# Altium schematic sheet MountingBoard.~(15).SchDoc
size Legal; Organization: Altium Limited; Address1: 3 Minna Close; Address2: Belrose; Address3: NSW 2085; Address4: Australia
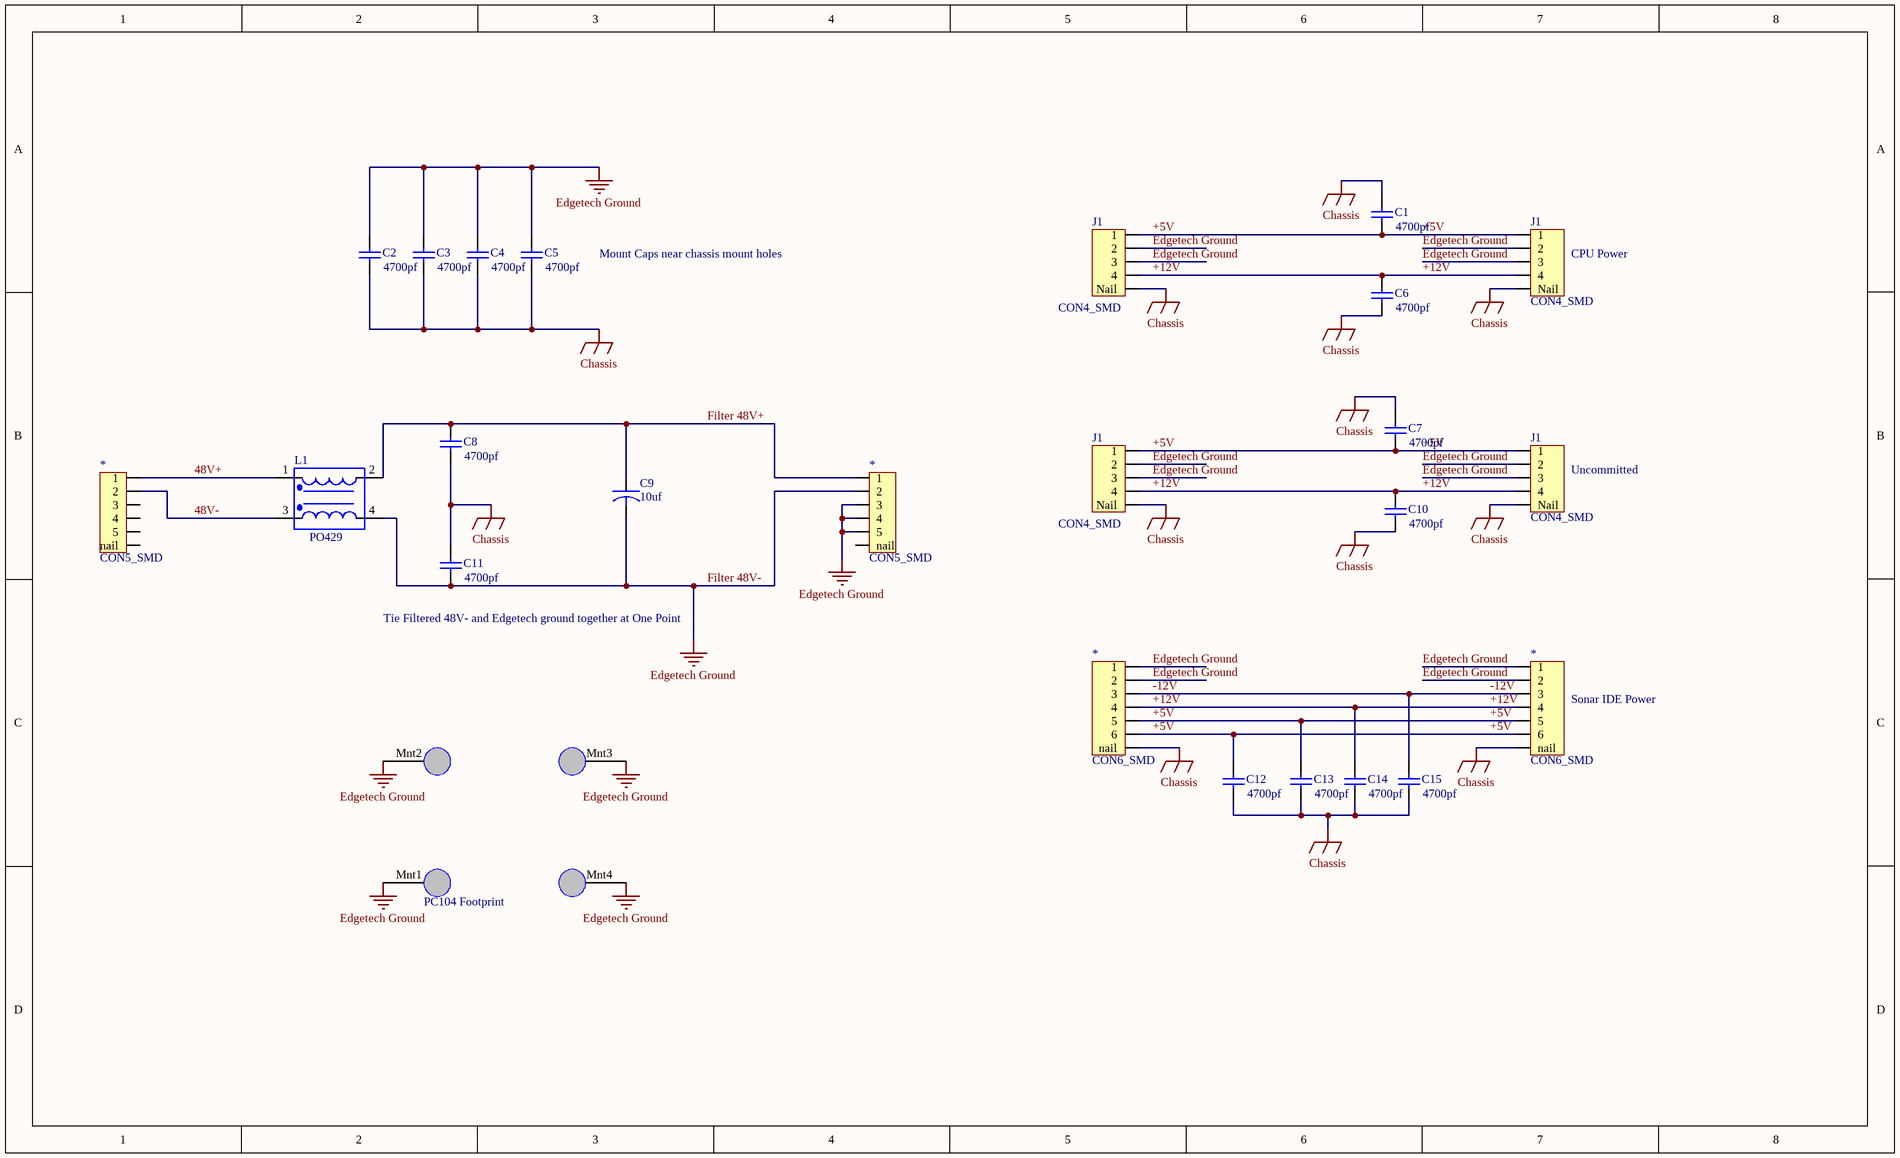
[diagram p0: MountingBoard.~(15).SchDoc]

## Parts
(Parts that share a designator on the sheet are numbered #1, #2 ... from top to bottom, then left to right.)
*#1  CON5_SMD  [Microfit3-1x5 SMT RA Nail]
*#2  CON5_SMD  [Microfit3-1x5 SMT RA Nail]
*#3  CON6_SMD  [Microfit3-1x6 SMT RA Nail]
*#4  CON6_SMD  [Microfit3-1x6 SMT RA Nail]
C1  value 4700pf  [7163]  (hidden comment: Cap Semi)
C2  value 4700pf  [7163]  (hidden comment: Cap Semi)
C3  value 4700pf  [7163]  (hidden comment: Cap Semi)
C4  value 4700pf  [7163]  (hidden comment: Cap Semi)
C5  value 4700pf  [7163]  (hidden comment: Cap Semi)
C6  value 4700pf  [7163]  (hidden comment: Cap Semi)
C7  value 4700pf  [7163]  (hidden comment: Cap Semi)
C8  value 4700pf  [7163]  (hidden comment: Cap Semi)
C9  10uf  [CAPSTICK-CS4-7-SMD]
C10  value 4700pf  [7163]  (hidden comment: Cap Semi)
C11  value 4700pf  [7163]  (hidden comment: Cap Semi)
C12  value 4700pf  [7163]  (hidden comment: Cap Semi)
C13  value 4700pf  [7163]  (hidden comment: Cap Semi)
C14  value 4700pf  [7163]  (hidden comment: Cap Semi)
C15  value 4700pf  [7163]  (hidden comment: Cap Semi)
F1  PC104 Footprint  [PC104 Footprint]
J1#1  CON4_SMD  [Microfit3-1x4 SMT RA Nail]
J1#2  CON4_SMD  [Microfit3-1x4 SMT RA Nail]
J1#3  CON4_SMD  [Microfit3-1x4 SMT RA Nail]
J1#4  CON4_SMD  [Microfit3-1x4 SMT RA Nail]
L1  ManufPartNo: PO429  [Pulse_BigFoot]

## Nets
Chassis: *#3.nail *#4.nail C1.2 C2.1 C3.1 C4.1 C5.1 C6.1 C7.2 C8.1 C10.1 C11.2 C12.1 C13.1 C14.1 C15.1 J1#1.nail(Nail) J1#2.nail(Nail) J1#3.nail(Nail) J1#4.nail(Nail)
Edgetech Ground: *#2.2 *#2.3 *#2.4 *#2.5 *#3.1 *#3.2 *#4.1 *#4.2 C2.2 C3.2 C4.2 C5.2 C9.2 C11.1 J1#1.2 J1#1.3 J1#2.2 J1#2.3 J1#3.2 J1#3.3 J1#4.2 J1#4.3 L1.4  [also labelled Filter 48V-]
48V+: *#1.1 L1.1
48V-: *#1.2 L1.3
+5V: *#3.5 *#3.6 *#4.5 *#4.6 C1.1 C7.1 C12.2 C13.2 J1#1.1 J1#2.1 J1#3.1 J1#4.1
+12V: *#3.4 *#4.4 C6.2 C10.2 C14.2 J1#1.4 J1#2.4 J1#3.4 J1#4.4
-12V: *#3.3 *#4.3 C15.2
Filter 48V+: *#2.1 C8.2 C9.1 L1.2

Not connected (* = marked no-connect by the designer): *#1 3 4 5 nail; *#2 nail; F1 Mnt1 Mnt2 Mnt3 Mnt4

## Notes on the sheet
- Mount Caps near chassis mount holes
- (near J1#2) CPU Power
- (near J1#4) Uncommitted
- (near C11) Tie Filtered 48V- and Edgetech ground together at One Point
- (near *#4) Sonar IDE Power
- Labels drawn without touching a wire or pin: Edgetech Ground

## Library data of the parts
C1-C8 C10-C15 = Cap Semi: Capacitor (Semiconductor SIM Model); Manufacturer: Panasonic; ManufPartNo: ECK-TBC472MF; VendorPartNo: P10743TR-ND; Vendor: Digikey
C9 = CAPACITOR: ManufPartNo: 106K100CS4G; Manufacturer: ITW Paktron; Vendor: Future Electronics; Value: 10
L1 = COMMON MODE CHOKE: Manufacturer: Pulse Engineering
